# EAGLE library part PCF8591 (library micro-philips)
I2C-Bus D/A CONVERTER
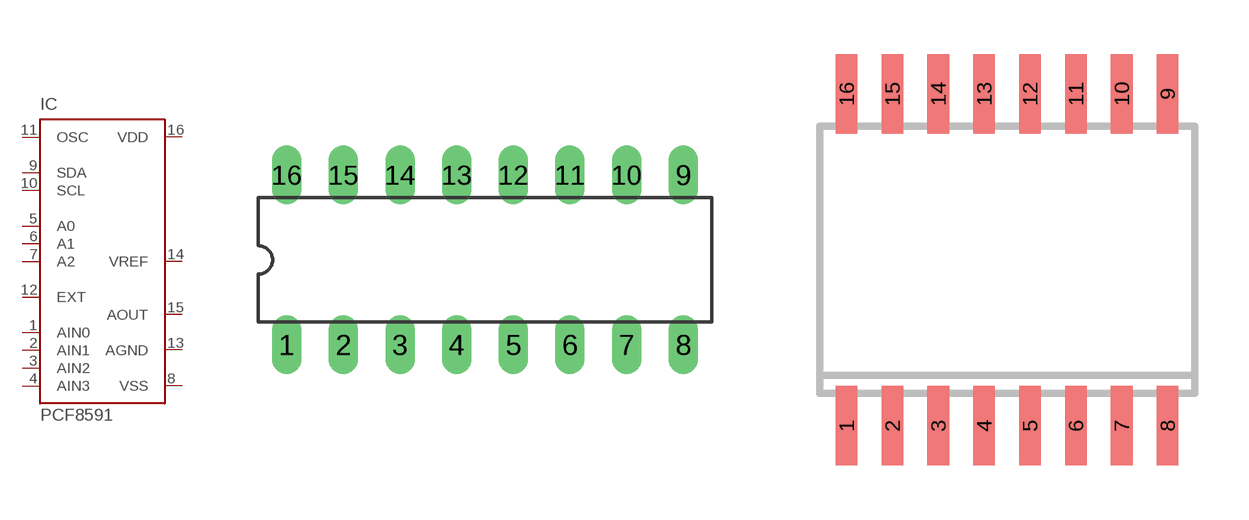
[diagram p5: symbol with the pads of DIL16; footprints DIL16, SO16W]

Designator prefix IC

## PCF8591P (MF: FARNELL; MPN: PCF8591P; OC_FARNELL: 396412; OC_NEWARK: 07WX3385)  [DIL16]
1  AIN0  in
2  AIN1  in
3  AIN2  in
4  AIN3  in
5  A0  in
6  A1  in
7  A2  in
8  VSS  pwr
9  SDA
10  SCL  in
11  OSC  in
12  EXT  in
13  AGND  pwr
14  VREF  in
15  AOUT  out
16  VDD  pwr

## PCF8591T (MPN: PCF8591T/2,512; OC_FARNELL: 1826767; OC_NEWARK: 70R6911)  [SO16W]
Pads as for DIL16

## Footprint DIL16 (pad centres in mm)
Dual In Line
drill 0.813 long: 1 -8.89,-3.81; 2 -6.35,-3.81; 3 -3.81,-3.81; 4 -1.27,-3.81; 5 1.27,-3.81; 6 3.81,-3.81; 7 6.35,-3.81; 8 8.89,-3.81; 9 8.89,3.81; 10 6.35,3.81; 11 3.81,3.81; 12 1.27,3.81; 13 -1.27,3.81; 14 -3.81,3.81; 15 -6.35,3.81; 16 -8.89,3.81

## Footprint SO16W (pad centres in mm)
Small Outline Package 7.6 x 10.6 mm
smd 0.6 x 2.2: 1 -4.445,-4.6; 2 -3.175,-4.6; 3 -1.905,-4.6; 4 -0.635,-4.6; 5 0.635,-4.6; 6 1.905,-4.6; 7 3.175,-4.6; 8 4.445,-4.6; 9 4.445,4.6; 10 3.175,4.6; 11 1.905,4.6; 12 0.635,4.6; 13 -0.635,4.6; 14 -1.905,4.6; 15 -3.175,4.6; 16 -4.445,4.6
